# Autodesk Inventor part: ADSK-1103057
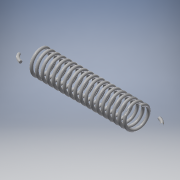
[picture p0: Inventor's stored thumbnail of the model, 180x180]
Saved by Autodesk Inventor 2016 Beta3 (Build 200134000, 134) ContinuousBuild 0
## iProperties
Shininess: 20.0
Length Units: 11269
Angle Units: 11279
Time Units: 11290
Mass Units: 11283
Length Display Precision: 3
Angle Display Precision: 2
Created: 2001-06
Part Number: ADSK-1103057
Material: Steel, Mild
Document SubType Name: Modeling
Description: UHAN #3.873-ESX
Mass: 0.263888 g
Surface Area: 2.99213 cm^2
Volume: 0.0335735 cm^3
Density: 7.86 g/cm^3
Appearance: Steel
Density: 7.86
Volumn: 3.5806394370622003
Area: 32.24046301072255
PropertySet Name: Model Information
Control State: 0
Master: False
Checked Out: False
msp_n: 18.000 ul
+MSCProtocol1+ProtocolID: P00060125011928546
+MSCProtocol2+Protocol: P00060125011928546<@PID>[Version]<@EL>Version=2.2<@EL>[Material]<@EL>MatID=<@EL>Material=User<@EL>Density=7850<@EL>[CalcData]<@EL>Scn1= 0<@EL>Scn2= 0<@EL>Scn3= 
Author: Autodesk, Inc.
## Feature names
1. Coil1
2. Revolution1
3. Sweep1
4. Sweep2
5. Revolution2
6. Sweep4
7. Sweep5
## Parameters: d0 = 1.7115 mm, d1 = 0.45 mm, prf_d = 0.45 mm, prf_D1 = 3.873 mm, d2 = 0.88844 mm, d4 = 185 mm, d5 = 0, d6 = 90 deg, d7 = 90 deg, d8 = 0, d9 = 0, prf_wl = 21 mm, prf_o = 2.504 mm, msp_L = 15.992 mm, d10 = -0.225 mm, d11 = 0.225 mm, d12 = 1.7115 mm, d14 = 90 deg, d15 = 1.0175 mm, d16 = 0, d17 = 0.45 mm, d18 = 0, d21 = 170 deg, d22 = 0.45 mm, d23 = 0, d24 = 0.225 mm, d25 = 90 deg, d29 = 16.21122 mm, d30 = 0, d31 = 1.7115 mm, d39 = 0.45 mm, d40 = 1.0175 mm, d41 = 0, d42 = 0, d43 = 170 deg, d44 = 0.45 mm, d45 = 0, d46 = 0, d47 = 0, d48 = 0, d49 = 0
